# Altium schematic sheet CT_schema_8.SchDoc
size 280 x 153 mm
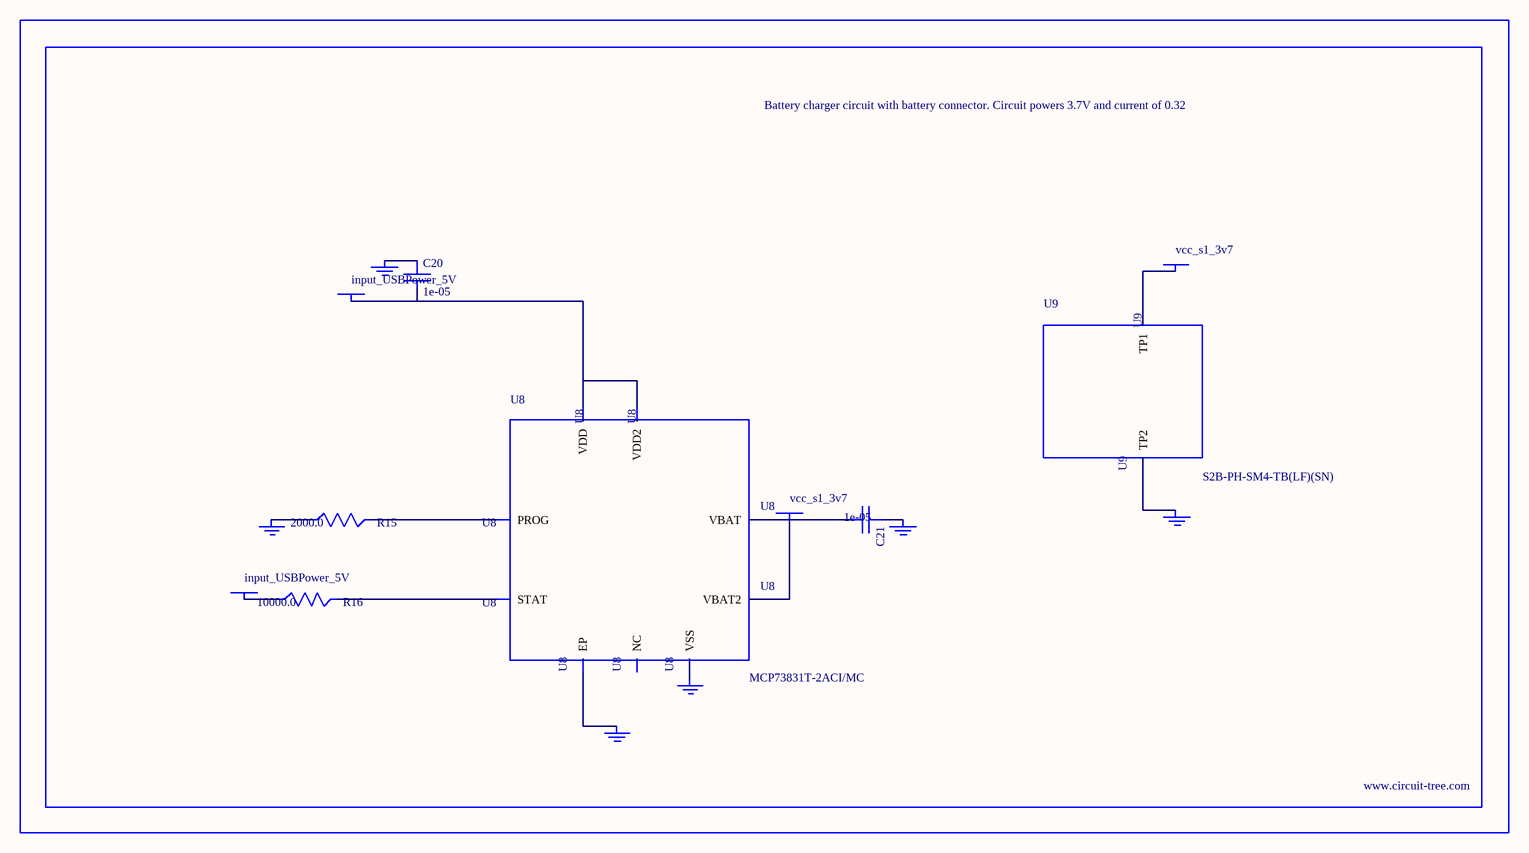
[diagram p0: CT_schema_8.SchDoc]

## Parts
BORDER7  (no value)
C20  1e-05  [C1206]
C21  1e-05  [C1206]
GND_INSTANCE_7_0  (no value)
GND_INSTANCE_7_1  (no value)
GND_INSTANCE_7_2  (no value)
GND_INSTANCE_7_3  (no value)
GND_INSTANCE_7_4  (no value)
GND_INSTANCE_7_5  (no value)
POWER_INSTANCE_7_0  input_USBPower_5V
POWER_INSTANCE_7_1  input_USBPower_5V
POWER_INSTANCE_7_2  vcc_s1_3v7
POWER_INSTANCE_7_3  vcc_s1_3v7
R15  2000.0  [R0603]
R16  10000.0  [R0603]
U8  MCP73831T-2ACI/MC  [DFN8_2X3MC]
U9  S2B-PH-SM4-TB(LF)(SN)  [JST-2-SMD]

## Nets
NetC20_1: C20.1 GND_INSTANCE_7_0.0(GND)
NetC20_2: C20.2 POWER_INSTANCE_7_0.0(PWR) U8.1(VDD) U8.2(VDD2)
NetC21_1: C21.1 GND_INSTANCE_7_1.0(GND)
NetC21_2: C21.2 POWER_INSTANCE_7_2.0(PWR) U8.3(VBAT) U8.4(VBAT2)
NetGND_INSTANCE_7_2_0: GND_INSTANCE_7_2.0(GND) R15.1
NetGND_INSTANCE_7_3_0: GND_INSTANCE_7_3.0(GND) U8.9(EP)
NetGND_INSTANCE_7_4_0: GND_INSTANCE_7_4.0(GND) U8.6(VSS)
NetGND_INSTANCE_7_5_0: GND_INSTANCE_7_5.0(GND) U9.2(TP2)
NetPOWER_INSTANCE_7_1_0: POWER_INSTANCE_7_1.0(PWR) R16.1
NetPOWER_INSTANCE_7_3_0: POWER_INSTANCE_7_3.0(PWR) U9.1(TP1)
NetR15_2: R15.2 U8.8(PROG)
NetR16_2: R16.2 U8.5(STAT)

Not connected (* = marked no-connect by the designer): U8 7(NC)

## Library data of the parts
BORDER7 = BORDER_PAGE7
C20 C21 = C1206C106K3RACTU
GND_INSTANCE_7_0-GND_INSTANCE_7_5 = GND
POWER_INSTANCE_7_0-POWER_INSTANCE_7_3 = PWR
R15 = RC0603JR-072KL
R16 = RC0603JR-0710KL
